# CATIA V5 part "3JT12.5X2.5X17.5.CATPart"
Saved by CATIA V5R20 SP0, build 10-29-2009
Part number: 3JT12.5X2.5X17.5
Revision: ANY
Definition: UNKNOWN
Nomenclature: 3JT12.5X2.5X17.5
Source: Unknown
Bounding box of the stored display mesh (mm): x -8.75 to 8.75, y -1.25 to 1.25, z -8.75 to 8.75
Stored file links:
  C:\Users\Utente\Desktop\IO LAVORO\3D X SITO CF\CUMSA\3D files PW\pw101630\pw101630_ejection\3JT12.5X2.5X17.5.CATPart
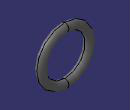
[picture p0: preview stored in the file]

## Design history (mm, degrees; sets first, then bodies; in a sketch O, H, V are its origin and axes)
Body1 "Revolución1" (main body)
  Solid1: solid without history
